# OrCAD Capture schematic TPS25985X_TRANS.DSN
size C
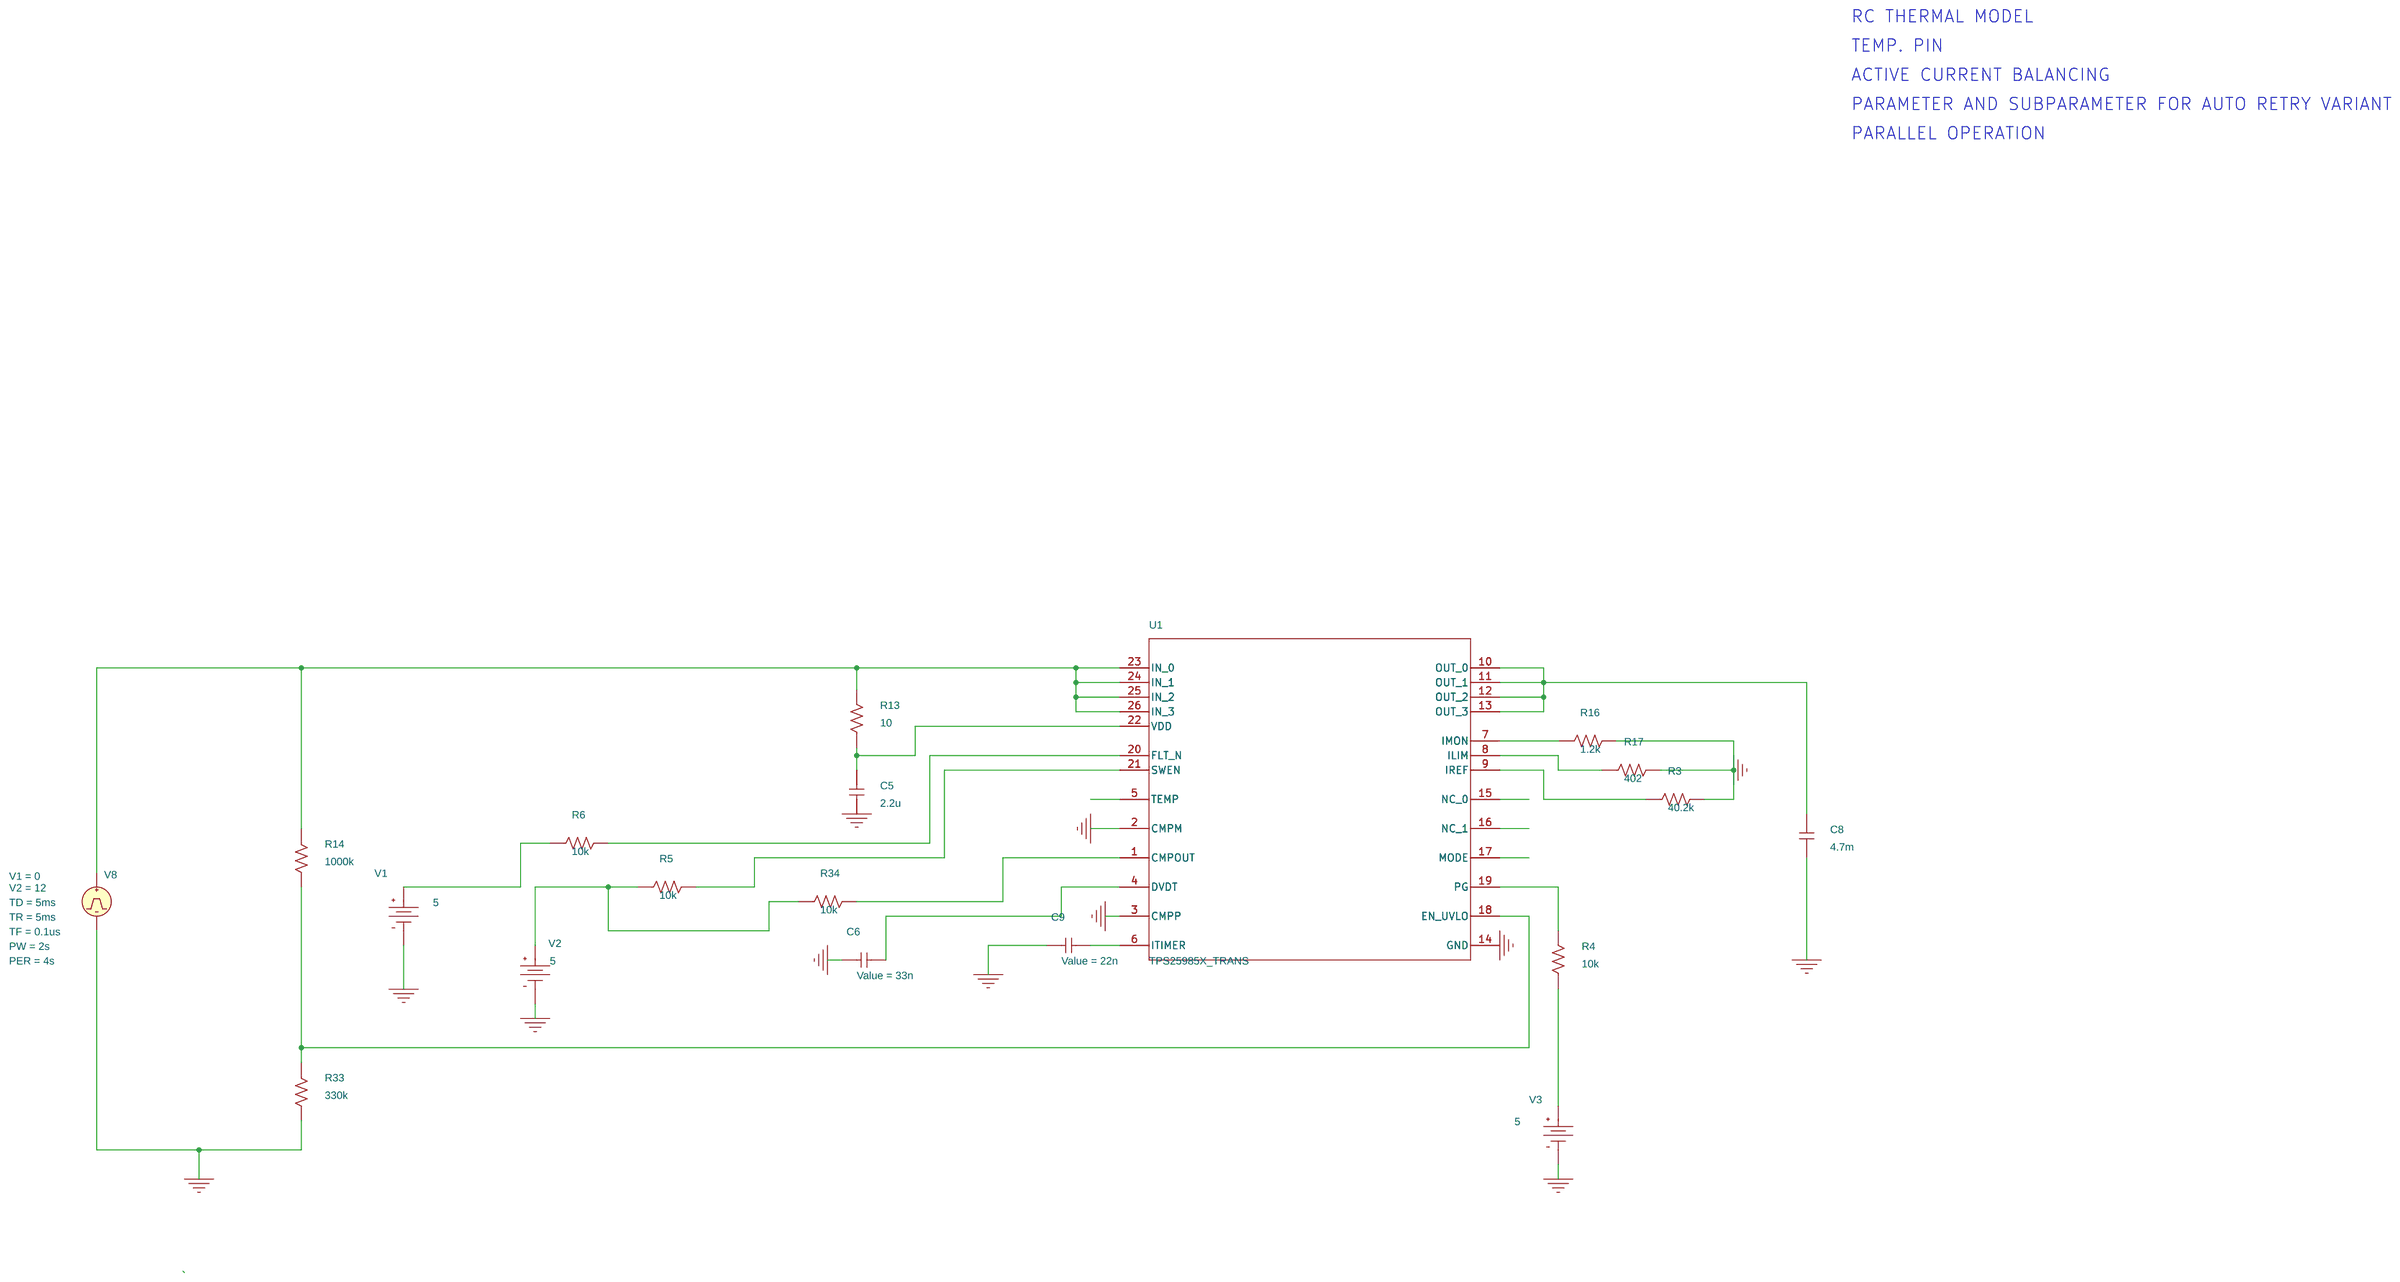
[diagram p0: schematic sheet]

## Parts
C5  2.2u  [RAD/CK05]
C6  33n  [cap196]
C8  4.7m  [RAD/CK05]
C9  22n  [cap196]
R3  40.2k  [AXRC05]
R4  10k  [AXRC05]
R5  10k  [AXRC05]
R6  10k  [AXRC05]
R13  10  [AX/RC05]
R14  1000k  [AX/RC05]
R16  1.2k  [AXRC05]
R17  402  [AXRC05]
R33  330k  [AX/RC05]
R34  10k  [AXRC05]
U1  Value  [RQP0026A-MFG]
V1  VDC
V2  VDC
V3  VDC
V8  VPULSE

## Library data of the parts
C5 C6 C8 C9 = C
R3-R6 R13 R14 R16 R17 R33 R34 = R
U1 = TPS25985RQP_TRANS: < Value >: TPS25985X_TRANS
V1-V3 = VDC: DC: 5
V8 = VPULSE: PER: 4s; PW: 2s; TD: 5ms; TF: 0.1us; TR: 5ms; V1: 0; V2: 12

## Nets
0: C5.1 C6.2 C8.1 C9.2 R3.2 R16.2 R17.2 R33.2 U1.2(CMPM) U1.3(CMPP) U1.14(GND) V1.1(-) V2.1(-) V3.1(-) V8.2(-)
N232350: C8.2 U1.10(OUT_0) U1.11(OUT_1) U1.12(OUT_2) U1.13(OUT_3)
N232382: R13.2 R14.1 U1.23(IN_0) U1.24(IN_1) U1.25(IN_2) U1.26(IN_3) V8.1(+)
N232692: R14.2 R33.1 U1.18(EN_UVLO)
N232718: R6.1 V1.0(+)
N232826: R5.1 R34.1 V2.0(+)
N254503: R16.1 U1.7(IMON)
N266879: C5.2 R13.1 U1.22(VDD)
N267116: R6.2 U1.20(FLT_N)
N267327: R5.2 U1.21(SWEN)
N267833: C6.1 U1.4(DVDT)
N276616: R4.1 V3.0(+)
N276877: C9.1 U1.6(ITIMER)
N277280: R4.2 U1.19(PG)
N277607: R17.1 U1.8(ILIM)
N277625: R3.1 U1.9(IREF)
N279461: R34.2 U1.1(CMPOUT)

Not connected (* = marked no-connect by the designer): U1 5(TEMP) 15(NC_0) 16(NC_1) 17(MODE)

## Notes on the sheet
- RC THERMAL MODEL
- TEMP. PIN
- ACTIVE CURRENT BALANCING
- PARAMETER AND SUBPARAMETER FOR AUTO RETRY VARIANT
- PARALLEL OPERATION
